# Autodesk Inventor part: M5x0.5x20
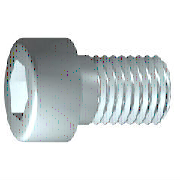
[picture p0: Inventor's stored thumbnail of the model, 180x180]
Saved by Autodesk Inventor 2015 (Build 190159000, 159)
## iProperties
IsCustomPart: 0
Created: 2009-02
Part Number: M5x0.5x20
Material: Steel, Mild
Description: 6각머리 태핑 나사
Document SubType Name: Modeling
Standard: KS B 1003
Designer: SeoGD™
Standards Organization: KS
Language: ko-KR
Size Designation: M 5 x 20
Categories: <MemberInstance><Categories><Category DisplayName="조임쇠" InternalName="e4da775c-781d-43d5-af7c-5136215cf5a6" Mnemonic="FSTN"><Category DisplayName="볼트" InternalN
Density: 1 g/cm^3
Appearance: Metal-Steel
Author: SeoGD™
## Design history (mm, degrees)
sketch "스케치1"
  geometry: L1 (-1.167, 0)-(20, 0); L2 (20, 0)-(20, 2.5); L3 (20, 2.5)-(2, 2.5); L4 (2, 2.5)-(1.509, 2.5); L5 (1.509, 2.5)-(0, 2.5); L6 (0, 2.5)-(0, 4.25); L7 (0, 4.25)-(-5, 4.25); L8 (-5, 4.25)-(-5, 2.309); L9 (-5, 2.309)-(-2.5, 2.309); L10 (-2.5, 2.309)-(-1.167, 0); L11 (-10, 0)-(25, 0) reference; L12 (0, -0.85)-(0, 5.1) reference; L13 (2, 2.5)-(0, 2.5)
  constraints: 22 end point, 6 parallel, 2 collinear, 2 perpendicular, 1 horizontal, 1 point on line
  dimensions: "d1" = 18 distance from line of L3.end L2 (= GEL); "d2" = 0.49086 distance of L4.end L3.end (computed from GAL); "d3" = 5 distance between parallel lines of L8 L6 (= KOH); "d4" = 2.5 distance of L8.end L9.end (= INTI); "d5" = 60 deg angle of L10 L1; "d6" = 5 diameter of L3 L1 (= GD); "d7" = 5 diameter of L5 L1 (= BDM); "d8" = 4.6188 diameter of L9 L1 (= 1.1547 x SW); "d9" = 8.5 diameter of L7 L1 (= KOD); "d26" = 20 distance between parallel lines of L12 L2 (= NLG)
revolve "본체" sketch "스케치1" stored, may be unused: angle "d10" = 90 deg
sketch "스케치2"
  geometry: L1 (0, -5.95)-(0, 5.95) reference; L2 (-5.95, 0)-(5.95, 0) reference; L3 (2.309, 0)-(1.155, -2); L4 (1.155, -2)-(-1.155, -2); L5 (-1.155, -2)-(-2.309, 0); L6 (-2.309, 0)-(-1.155, 2); L7 (-1.155, 2)-(1.155, 2); L8 (1.155, 2)-(2.309, 0); 2 further points
  constraints: 12 end point, 1 coincident, 1 horizontal alignment, 1 point on line, 12 other
extrude "슬롯" join sketch "스케치2" stored distance "d11" = 10; taper "d12" = 0 deg
workplane "Work Plane1"
fillet "Fillet2" dims "d30" = 0.1 (= R)
body "Solid1"
fillet "모깎기1" dims "d17" = 0.5 (= RR)
feature "스레드" dims "d13" = 18 (= GEL), "d14" = 0
chamfer "모따기1" distance "d15" = 0.49076 (= -0.5 x SPD + 0.5 x GD); stored, may be unused: second distance "d16" = 0.49076 (= GUL), angle "d27" = 45 deg
other parameters: "GD" = 5 (= NND) [user parameter; used in 2 equation terms], "NLG" = 20 [user parameter; used in 1 equation term], "GEL" = 18 [user parameter; used in 2 equation terms], "KOD" = 8.5 [user parameter; used in 1 equation term], "KOH" = 5 [user parameter; used in 1 equation term], "INTI" = 2.5 [user parameter; used in 1 equation term], "GAL" = 0.49076 (= 0.61345 x PTC) [user parameter; used in 1 equation term], "GUL" = 0.49076 (= 0.61345 x PTC) [user parameter; used in 1 equation term], "BDM" = 5 (= NND) [user parameter; used in 1 equation term], "SW" = 4 [user parameter; used in 2 equation terms], "RR" = 0.5 [user parameter; used in 1 equation term], "SPD" = 4.01848 (= NND - 1.2269 x PTC) [user parameter; used in 1 equation term], "d19" = 0, "d28" = 0, "d29" = 0, "R" = 0.1 [user parameter; used in 1 equation term], "PHH" = 0.2 [user parameter], "GD1" = 4.01848 (= THREADDIA - 1.2269 x PTC) [user parameter], "THREADDIA" = 5 [user parameter; used in 1 equation term], "FAWI" = 45 deg [user parameter], "TPU" = 12.5 (computed from PTC) [user parameter], "PTC" = 0.8 [user parameter; used in 5 equation terms], "NND" = 5 [user parameter; used in 3 equation terms], "TOA" = 30 deg [user parameter], "E0" = 4.62 (= 1.155 x SW) [user parameter]
